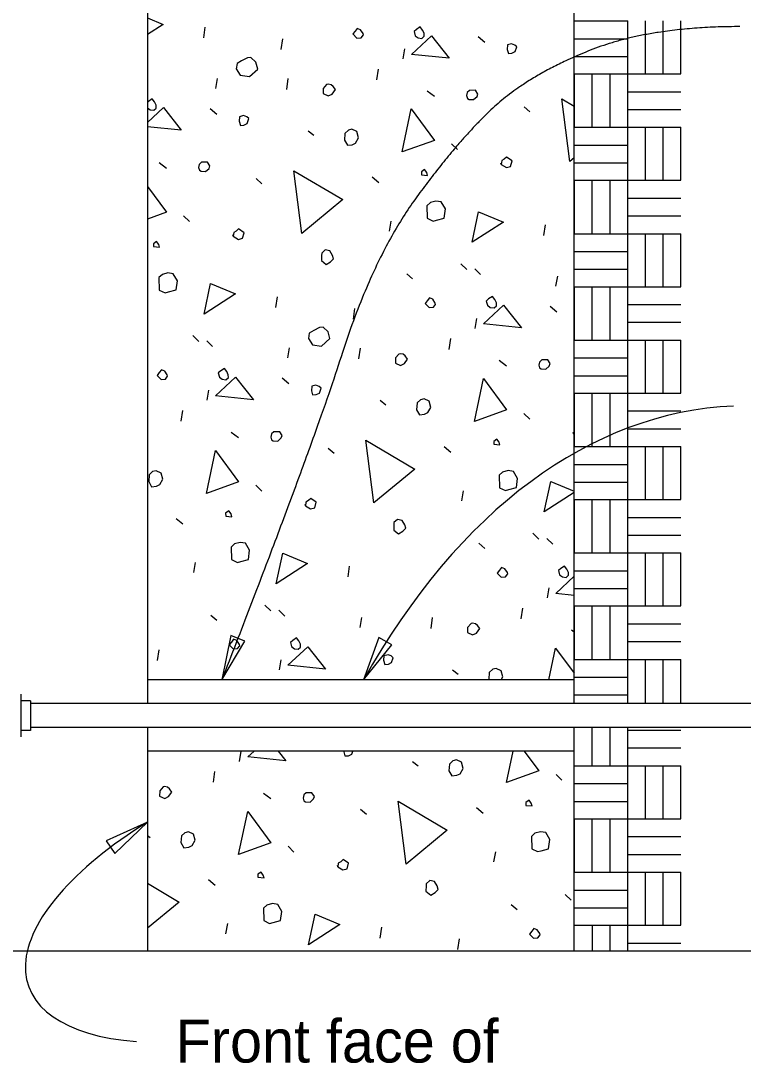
# Model space of a CAD drawing. Extents: x 0 to 30.8, y 0 to 21.2.
# Drawn here: x 25.516 to 28.054, y 11.993 to 15.653 of the extents above; entities that cross this region are included whole.
import ezdxf

# ---------------------------------------------------------------- set-up
doc = ezdxf.new("R2010")
doc.units = 0
for name, color, linetype in [('Dimension', 7, 'Continuous'), ('Lighting', 7, 'Continuous'), ('Miscellaneous', 7, 'Continuous'), ('SupstrConc', 7, 'Continuous')]:
    doc.layers.add(name, color=color, linetype=linetype)

msp = doc.modelspace()

# ---------------------------------------------------------------- linework, layer by layer
at = {"layer": 'Dimension'}
for points in [[(26.2225, 13.3392), (26.3038, 13.4751), (26.2545, 13.4943)], [(26.7207, 13.3388), (26.82, 13.4622), (26.7738, 13.488)], [(25.9607, 12.8391), (25.8165, 12.7736), (25.8461, 12.7297)]]:
    msp.add_lwpolyline(points, close=True, dxfattribs=at)
msp.add_lwpolyline([(28.7417, 12.3859), (25.4201, 12.3859), (25.4201, 12.4634), (25.3864, 12.3859), (25.3526, 12.3084), (25.3526, 12.3859), (20.9396, 12.3859)], dxfattribs=at)
for centre, major_axis, ratio, start_param, end_param in [((28.1525, 11.1408), (0.1319, -3.1595), 0.604161, 3.141595, 3.918123), ((26.5684, 12.6268), (1.0252, 0.3641), 0.417881, 2.049946, 3.892568)]:
    msp.add_ellipse(centre, major_axis=major_axis, ratio=ratio, start_param=start_param, end_param=end_param, dxfattribs=at)
msp.add_open_spline([(28.0429, 15.6332), (27.7261, 15.6332), (27.3087, 15.4672), (27.0623, 15.2459), (26.7555, 14.8283), (26.5342, 14.1391), (26.2224, 13.3392)], degree=2, dxfattribs=at)
at = {"layer": 'Lighting'}
for p, q in [((25.5162, 13.2888), (25.5162, 13.1389)), ((25.5496, 13.2658), (25.5162, 13.2658)), ((25.5496, 13.2658), (25.5496, 13.1617)), ((28.6643, 13.2555), (25.5496, 13.2555)), ((25.5496, 13.1617), (25.5162, 13.1617)), ((28.6643, 13.1721), (25.5496, 13.1721))]:
    msp.add_line(p, q, dxfattribs=at)
at = {"layer": 'Miscellaneous'}
for p, q in [((26.1587, 15.5936), (26.1641, 15.6313)), ((27.4607, 15.6534), (27.6495, 15.6534)), ((27.6495, 15.2797), (27.6495, 15.6534)), ((27.7107, 15.4672), (27.7107, 15.6534)), ((27.7732, 15.4672), (27.7732, 15.6534)), ((27.8357, 15.4672), (27.8357, 15.6534)), ((27.1228, 15.5983), (27.1462, 15.5787)), ((26.431, 15.5527), (26.4365, 15.5904)), ((27.4607, 15.5909), (27.6495, 15.5909)), ((26.8591, 15.5199), (26.8652, 15.5552)), ((27.4607, 15.5284), (27.6495, 15.5284)), ((26.2011, 15.416), (26.2072, 15.4513)), ((26.4504, 15.4129), (26.4558, 15.4506)), ((26.7676, 15.4462), (26.773, 15.4839)), ((27.4607, 15.4672), (27.8357, 15.4672)), ((27.4607, 15.4672), (27.4607, 15.2797)), ((27.5232, 15.4672), (27.5232, 15.2797)), ((27.5857, 15.4672), (27.5857, 15.2797)), ((26.9435, 15.4079), (26.9693, 15.3889)), ((27.6495, 15.4047), (27.8357, 15.4047)), ((26.181, 15.3459), (26.2044, 15.3263)), ((27.2846, 15.3518), (27.3049, 15.3339)), ((27.6495, 15.3422), (27.8357, 15.3422)), ((26.5256, 15.2674), (26.5453, 15.252)), ((27.4607, 15.2797), (27.6495, 15.2797)), ((27.6495, 14.9059), (27.6495, 15.2797)), ((27.6495, 15.2797), (27.8357, 15.2797)), ((27.7107, 15.0934), (27.7107, 15.2797)), ((27.7732, 15.0934), (27.7732, 15.2797)), ((27.8357, 15.0934), (27.8357, 15.2797)), ((27.0297, 15.2214), (27.0507, 15.2011)), ((27.4607, 15.2172), (27.6495, 15.2172)), ((26.0017, 15.1555), (26.0275, 15.1366)), ((27.4607, 15.1547), (27.6495, 15.1547)), ((26.3428, 15.0994), (26.3632, 15.0816)), ((26.7503, 15.1051), (26.7736, 15.0855)), ((27.4607, 15.0934), (27.8357, 15.0934)), ((27.4607, 15.0934), (27.4607, 14.9059)), ((27.5232, 15.0934), (27.5232, 14.9059)), ((27.5857, 15.0934), (27.5857, 14.9059)), ((27.6495, 15.0309), (27.8357, 15.0309)), ((26.0879, 14.969), (26.1089, 14.9487)), ((26.8117, 14.9145), (26.8178, 14.9497)), ((27.3541, 14.8993), (27.3595, 14.937)), ((27.6495, 14.9684), (27.8357, 14.9684)), ((27.4607, 14.9059), (27.6495, 14.9059)), ((27.6495, 14.9059), (27.8357, 14.9059)), ((27.6495, 14.5322), (27.6495, 14.9059)), ((27.7107, 14.7197), (27.7107, 14.9059)), ((27.7732, 14.7197), (27.7732, 14.9059)), ((27.8357, 14.7197), (27.8357, 14.9059)), ((27.4607, 14.8434), (27.6495, 14.8434)), ((27.0622, 14.8004), (27.0832, 14.7802)), ((26.8724, 14.7651), (26.8927, 14.7472)), ((27.1111, 14.7825), (27.132, 14.7622)), ((27.3965, 14.7218), (27.4026, 14.757)), ((27.4607, 14.7809), (27.6495, 14.7809)), ((27.4607, 14.7197), (27.8357, 14.7197)), ((27.4607, 14.7197), (27.4607, 14.5322)), ((27.5232, 14.7197), (27.5232, 14.5322)), ((27.5857, 14.7197), (27.5857, 14.5322)), ((26.4123, 14.647), (26.4177, 14.6847)), ((26.6847, 14.6061), (26.6901, 14.6438)), ((27.3765, 14.6517), (27.3998, 14.6321)), ((27.6495, 14.6572), (27.8357, 14.6572)), ((27.1128, 14.5733), (27.1188, 14.6085)), ((27.6495, 14.5947), (27.8357, 14.5947)), ((26.1205, 14.5481), (26.1414, 14.5278)), ((27.0212, 14.4996), (27.0266, 14.5373)), ((26.1693, 14.5301), (26.1902, 14.5098)), ((26.4547, 14.4694), (26.4608, 14.5047)), ((26.704, 14.4663), (26.7094, 14.504)), ((27.4607, 14.5322), (27.6495, 14.5322)), ((27.6495, 14.1584), (27.6495, 14.5322)), ((27.6495, 14.5322), (27.8357, 14.5322)), ((27.7107, 14.3459), (27.7107, 14.5322)), ((27.7732, 14.3459), (27.7732, 14.5322)), ((27.8357, 14.3459), (27.8357, 14.5322)), ((27.1971, 14.4613), (27.2229, 14.4423)), ((27.4607, 14.4697), (27.6495, 14.4697)), ((26.4347, 14.3993), (26.458, 14.3797)), ((27.4607, 14.4072), (27.6495, 14.4072)), ((26.171, 14.3209), (26.1771, 14.3562)), ((26.7792, 14.3208), (26.7989, 14.3054)), ((27.4607, 14.3459), (27.8357, 14.3459)), ((27.4607, 14.3459), (27.4607, 14.1584)), ((27.5232, 14.3459), (27.5232, 14.1584)), ((27.5857, 14.3459), (27.5857, 14.1584)), ((26.0794, 14.2472), (26.0849, 14.2849)), ((27.6495, 14.2834), (27.8357, 14.2834)), ((27.2833, 14.2747), (27.3043, 14.2545)), ((26.2553, 14.2089), (26.2811, 14.19)), ((27.6495, 14.2209), (27.8357, 14.2209)), ((26.5965, 14.1528), (26.6168, 14.135)), ((27.0039, 14.1585), (27.0273, 14.1388)), ((27.4607, 14.1584), (27.6495, 14.1584)), ((27.6495, 13.7847), (27.6495, 14.1584)), ((27.6495, 14.1584), (27.8357, 14.1584)), ((27.7107, 13.9722), (27.7107, 14.1584)), ((27.7732, 13.9722), (27.7732, 14.1584)), ((27.8357, 13.9722), (27.8357, 14.1584)), ((27.4607, 14.0959), (27.6495, 14.0959)), ((26.3416, 14.0224), (26.3625, 14.0021)), ((27.4607, 14.0334), (27.6495, 14.0334)), ((27.0653, 13.9679), (27.0714, 14.0031)), ((27.4607, 13.9722), (27.8357, 13.9722)), ((27.4607, 13.9722), (27.4607, 13.7847)), ((27.5232, 13.9722), (27.5232, 13.7847)), ((27.5857, 13.9722), (27.5857, 13.7847)), ((26.0621, 13.9061), (26.0855, 13.8865)), ((27.6495, 13.9097), (27.8357, 13.9097)), ((27.3159, 13.8538), (27.3368, 13.8336)), ((27.6495, 13.8472), (27.8357, 13.8472)), ((27.1261, 13.8185), (27.1464, 13.8006)), ((27.3647, 13.8358), (27.3857, 13.8156)), ((27.4607, 13.7847), (27.6495, 13.7847)), ((27.6495, 13.7847), (27.8357, 13.7847)), ((27.6495, 13.4109), (27.6495, 13.7847)), ((27.7107, 13.5984), (27.7107, 13.7847)), ((27.7732, 13.5984), (27.7732, 13.7847)), ((27.8357, 13.5984), (27.8357, 13.7847)), ((26.1236, 13.7155), (26.1296, 13.7508)), ((26.666, 13.7004), (26.6714, 13.7381)), ((27.4607, 13.7222), (27.6495, 13.7222)), ((27.3664, 13.6267), (27.3725, 13.6619)), ((27.4607, 13.6597), (27.6495, 13.6597)), ((26.3741, 13.6015), (26.3951, 13.5812)), ((26.4229, 13.5835), (26.4439, 13.5632)), ((27.2749, 13.553), (27.2803, 13.5906)), ((27.4607, 13.5984), (27.8357, 13.5984)), ((27.4607, 13.5984), (27.4607, 13.4109)), ((27.5232, 13.5984), (27.5232, 13.4109)), ((27.5857, 13.5984), (27.5857, 13.4109)), ((26.1843, 13.5661), (26.2046, 13.5483)), ((26.7084, 13.5228), (26.7144, 13.5581)), ((26.9577, 13.5197), (26.9631, 13.5574)), ((27.4508, 13.5147), (27.4607, 13.5073)), ((27.6495, 13.5359), (27.8357, 13.5359)), ((27.6495, 13.4734), (27.8357, 13.4734)), ((25.9965, 13.4071), (26.002, 13.4448)), ((26.4246, 13.3743), (26.4307, 13.4096)), ((27.4607, 13.4109), (27.6495, 13.4109)), ((27.6495, 13.2555), (27.6495, 13.411)), ((27.6495, 13.4109), (27.8357, 13.4109)), ((27.7107, 13.2555), (27.7107, 13.411)), ((27.7732, 13.2555), (27.7732, 13.411)), ((27.8357, 13.2555), (27.8357, 13.411)), ((27.0329, 13.3742), (27.0525, 13.3588)), ((27.4607, 13.3388), (25.9607, 13.3388)), ((27.4607, 13.3484), (27.6495, 13.3484)), ((27.4607, 13.2859), (27.6495, 13.2859)), ((27.5232, 13.1721), (27.5232, 13.0372)), ((27.5857, 13.1721), (27.5857, 13.0372)), ((27.6495, 13.0372), (27.6495, 13.1721)), ((27.6495, 13.1622), (27.8357, 13.1622)), ((27.4607, 13.0888), (25.9607, 13.0888)), ((26.2844, 13.0528), (26.2905, 13.0881)), ((27.6495, 13.0997), (27.8357, 13.0997)), ((26.8927, 13.0527), (26.9123, 13.0373)), ((27.4607, 13.0372), (27.6495, 13.0372)), ((27.6495, 12.6634), (27.6495, 13.0372)), ((27.6495, 13.0372), (27.8357, 13.0372)), ((27.7107, 12.8509), (27.7107, 13.0372)), ((27.7732, 12.8509), (27.7732, 13.0372)), ((27.8357, 12.8509), (27.8357, 13.0372)), ((26.1929, 12.9791), (26.1983, 13.0168)), ((27.3968, 13.0066), (27.4177, 12.9864)), ((27.4607, 12.9747), (27.6495, 12.9747)), ((26.3688, 12.9408), (26.3946, 12.9218)), ((27.1174, 12.8903), (27.1407, 12.8707)), ((27.4607, 12.9122), (27.6495, 12.9122)), ((26.7099, 12.8847), (26.7303, 12.8668)), ((27.4607, 12.8509), (27.8357, 12.8509)), ((27.4607, 12.8509), (27.4607, 12.6634)), ((27.5232, 12.8509), (27.5232, 12.6634)), ((27.5857, 12.8509), (27.5857, 12.6634)), ((25.9607, 12.7926), (25.9706, 12.7849)), ((27.6495, 12.7884), (27.8357, 12.7884)), ((26.455, 12.7543), (26.476, 12.734)), ((27.1788, 12.6997), (27.1849, 12.735)), ((27.6495, 12.7259), (27.8357, 12.7259)), ((26.1756, 12.638), (26.199, 12.6184)), ((27.4607, 12.6634), (27.6495, 12.6634)), ((27.6495, 12.386), (27.6495, 12.6635)), ((27.6495, 12.6634), (27.8357, 12.6634)), ((27.7107, 12.4772), (27.7107, 12.6634)), ((27.7732, 12.4772), (27.7732, 12.6634)), ((27.8357, 12.4772), (27.8357, 12.6634)), ((27.4607, 12.6009), (27.6495, 12.6009)), ((27.4293, 12.5857), (27.4503, 12.5654)), ((27.2395, 12.5504), (27.2598, 12.5325)), ((27.4607, 12.5384), (27.6495, 12.5384)), ((26.237, 12.4474), (26.2431, 12.4827)), ((26.7794, 12.4323), (26.7848, 12.47)), ((27.4607, 12.4772), (27.8357, 12.4772)), ((27.5233, 12.4772), (27.5233, 12.386)), ((27.5858, 12.4772), (27.5858, 12.386)), ((27.0518, 12.3914), (27.0572, 12.4291)), ((27.6495, 12.4147), (27.8357, 12.4147))]:
    msp.add_line(p, q, dxfattribs=at)
for points in [[(25.9607, 15.664), (26.0166, 15.6409), (25.9607, 15.605)], [(26.902, 15.6013), (26.9119, 15.5935), (26.9252, 15.5919), (26.9336, 15.5994), (26.9334, 15.6097), (26.9278, 15.6211), (26.9197, 15.6319), (26.9065, 15.6232), (26.8981, 15.6157), (26.902, 15.6013)], [(26.683, 15.6073), (26.6972, 15.593), (26.7123, 15.5944), (26.72, 15.6043), (26.7187, 15.6091), (26.71, 15.6223), (26.6984, 15.6269), (26.6907, 15.6171), (26.683, 15.6073)], [(26.8886, 15.5355), (26.959, 15.601), (27.0216, 15.522), (26.8886, 15.5355)], [(27.2254, 15.5533), (27.2293, 15.5388), (27.242, 15.5397), (27.2535, 15.5453), (27.2593, 15.5624), (27.2525, 15.5683), (27.2409, 15.573), (27.2264, 15.5691), (27.2254, 15.5533)], [(26.2733, 15.4846), (26.287, 15.4623), (26.3192, 15.458), (26.3485, 15.484), (26.342, 15.5081), (26.3248, 15.5242), (26.3121, 15.5234), (26.2916, 15.5128), (26.276, 15.5034), (26.2733, 15.4846)], [(26.5789, 15.4163), (26.5786, 15.3981), (26.5963, 15.3899), (26.6101, 15.3962), (26.6214, 15.4122), (26.6133, 15.423), (26.6066, 15.4289), (26.5956, 15.4311), (26.5908, 15.4299), (26.5789, 15.4163)], [(25.9607, 15.3485), (25.9701, 15.3412), (25.9834, 15.3396), (25.9918, 15.347), (25.9916, 15.3573), (25.986, 15.3687), (25.9779, 15.3795), (25.9647, 15.3708), (25.9607, 15.3673)], [(27.0852, 15.3812), (27.0913, 15.3776), (27.1071, 15.3767), (27.1197, 15.3878), (27.1226, 15.3964), (27.1139, 15.4095), (27.0932, 15.4092), (27.0849, 15.4018), (27.0826, 15.3908), (27.0852, 15.3812)], [(27.4449, 15.1592), (27.417, 15.3795), (27.4607, 15.3537)], [(25.9607, 15.2961), (26.0173, 15.3486), (26.0798, 15.2697), (25.9607, 15.2818)], [(26.8561, 15.193), (26.8882, 15.3439), (26.9695, 15.2337), (26.8561, 15.193)], [(26.2837, 15.301), (26.2875, 15.2865), (26.3003, 15.2873), (26.3117, 15.293), (26.3175, 15.31), (26.3107, 15.316), (26.2991, 15.3206), (26.2846, 15.3168), (26.2837, 15.301)], [(26.6549, 15.2581), (26.6535, 15.2344), (26.6635, 15.2164), (26.681, 15.2185), (26.6925, 15.2242), (26.7031, 15.2425), (26.6973, 15.2643), (26.6795, 15.2725), (26.6675, 15.2692), (26.6549, 15.2581)], [(26.1434, 15.1288), (26.1496, 15.1253), (26.1654, 15.1243), (26.1779, 15.1355), (26.1808, 15.144), (26.1721, 15.1572), (26.1515, 15.1569), (26.1431, 15.1494), (26.1409, 15.1385), (26.1434, 15.1288)], [(27.2043, 15.1491), (27.2227, 15.1385), (27.2372, 15.1424), (27.2423, 15.1619), (27.2233, 15.1749), (27.215, 15.1675), (27.2059, 15.1625), (27.2043, 15.1491), (27.2031, 15.1539)], [(27.4607, 15.1722), (27.4449, 15.1592)], [(26.5032, 14.9069), (26.4752, 15.1271), (26.6473, 15.0257), (26.5032, 14.9069)], [(26.9242, 15.1128), (26.9454, 15.1108), (26.9429, 15.1204), (26.9348, 15.1312), (26.924, 15.1232), (26.9242, 15.1128)], [(25.9607, 15.0721), (26.0277, 14.9813), (25.9607, 14.9573)], [(26.943, 15.004), (26.9443, 14.9604), (26.9651, 14.9504), (26.9772, 14.9536), (27.0038, 14.9608), (27.0081, 14.993), (26.9937, 15.0176), (26.9749, 15.0203), (26.9555, 15.0151), (26.943, 15.004)], [(27.1016, 14.8757), (27.1247, 14.9828), (27.212, 14.9467), (27.1016, 14.8757)], [(26.2626, 14.8967), (26.2809, 14.8861), (26.2954, 14.89), (26.3006, 14.9095), (26.2815, 14.9225), (26.2732, 14.9151), (26.2642, 14.9101), (26.2626, 14.8967), (26.2613, 14.9016)], [(25.9824, 14.8605), (26.0037, 14.8584), (26.0011, 14.8681), (25.993, 14.8789), (25.9822, 14.8708), (25.9824, 14.8605)], [(26.573, 14.8298), (26.5727, 14.8116), (26.5893, 14.7979), (26.6049, 14.8073), (26.615, 14.8178), (26.6118, 14.8298), (26.6024, 14.8455), (26.586, 14.8488), (26.5734, 14.8377), (26.573, 14.8298)], [(26.0012, 14.7517), (26.0026, 14.708), (26.0233, 14.6981), (26.0354, 14.7013), (26.062, 14.7084), (26.0663, 14.7406), (26.0519, 14.7652), (26.0331, 14.768), (26.0138, 14.7628), (26.0012, 14.7517)], [(26.1598, 14.6233), (26.1829, 14.7305), (26.2702, 14.6943), (26.1598, 14.6233)], [(26.9366, 14.6607), (26.9508, 14.6463), (26.966, 14.6478), (26.9737, 14.6576), (26.9724, 14.6625), (26.9637, 14.6757), (26.9521, 14.6803), (26.9444, 14.6705), (26.9366, 14.6607)], [(27.1557, 14.6546), (27.1655, 14.6469), (27.1789, 14.6453), (27.1872, 14.6527), (27.1871, 14.6631), (27.1814, 14.6745), (27.1733, 14.6853), (27.1601, 14.6766), (27.1518, 14.6691), (27.1557, 14.6546)], [(27.1422, 14.5889), (27.2127, 14.6544), (27.2752, 14.5754), (27.1422, 14.5889)], [(26.5269, 14.5379), (26.5407, 14.5157), (26.5729, 14.5114), (26.6021, 14.5374), (26.5957, 14.5615), (26.5784, 14.5776), (26.5657, 14.5768), (26.5453, 14.5661), (26.5297, 14.5568), (26.5269, 14.5379)], [(26.8325, 14.4697), (26.8322, 14.4515), (26.8499, 14.4433), (26.8638, 14.4496), (26.875, 14.4656), (26.867, 14.4764), (26.8602, 14.4823), (26.8492, 14.4845), (26.8444, 14.4832), (26.8325, 14.4697)], [(27.3389, 14.4346), (27.345, 14.431), (27.3608, 14.4301), (27.3733, 14.4412), (27.3762, 14.4497), (27.3675, 14.4629), (27.3469, 14.4626), (27.3385, 14.4552), (27.3363, 14.4442), (27.3389, 14.4346)], [(25.9949, 14.4083), (26.0091, 14.394), (26.0242, 14.3955), (26.0319, 14.4053), (26.0306, 14.4101), (26.0219, 14.4233), (26.0103, 14.428), (26.0026, 14.4181), (25.9949, 14.4083)], [(26.2139, 14.4023), (26.2237, 14.3946), (26.2371, 14.393), (26.2455, 14.4004), (26.2453, 14.4107), (26.2396, 14.4221), (26.2316, 14.4329), (26.2184, 14.4242), (26.21, 14.4168), (26.2139, 14.4023)], [(26.2004, 14.3366), (26.2709, 14.402), (26.3335, 14.323), (26.2004, 14.3366)], [(27.1098, 14.2464), (27.1418, 14.3973), (27.2231, 14.2871), (27.1098, 14.2464)], [(26.5373, 14.3544), (26.5412, 14.3399), (26.5539, 14.3407), (26.5653, 14.3464), (26.5711, 14.3634), (26.5643, 14.3694), (26.5527, 14.374), (26.5383, 14.3702), (26.5373, 14.3544)], [(26.9086, 14.3115), (26.9071, 14.2878), (26.9171, 14.2698), (26.9347, 14.2719), (26.9461, 14.2776), (26.9567, 14.2959), (26.9509, 14.3177), (26.9332, 14.3259), (26.9211, 14.3226), (26.9086, 14.3115)], [(26.3971, 14.1822), (26.4032, 14.1787), (26.419, 14.1777), (26.4315, 14.1889), (26.4344, 14.1974), (26.4257, 14.2106), (26.4051, 14.2102), (26.3967, 14.2028), (26.3945, 14.1919), (26.3971, 14.1822)], [(27.4607, 14.2165), (27.4596, 14.2159), (27.458, 14.2025), (27.4567, 14.2073)], [(26.7568, 13.9602), (26.7288, 14.1805), (26.9009, 14.0791), (26.7568, 13.9602)], [(27.1778, 14.1662), (27.1991, 14.1642), (27.1965, 14.1738), (27.1884, 14.1846), (27.1777, 14.1765), (27.1778, 14.1662)], [(27.458, 14.2025), (27.4607, 14.2009)], [(26.168, 13.994), (26.2, 14.1449), (26.2813, 14.0347), (26.168, 13.994)], [(25.9668, 14.0591), (25.9654, 14.0355), (25.9754, 14.0174), (25.9929, 14.0196), (26.0043, 14.0252), (26.0149, 14.0436), (26.0091, 14.0653), (25.9914, 14.0735), (25.9793, 14.0703), (25.9668, 14.0591)], [(27.1966, 14.0574), (27.198, 14.0138), (27.2188, 14.0038), (27.2308, 14.007), (27.2574, 14.0142), (27.2617, 14.0464), (27.2473, 14.071), (27.2285, 14.0737), (27.2092, 14.0685), (27.1966, 14.0574)], [(27.3553, 13.9291), (27.3783, 14.0362), (27.4607, 14.0021)], [(27.4607, 13.9969), (27.3553, 13.9291)], [(26.5162, 13.9501), (26.5346, 13.9395), (26.5491, 13.9434), (26.5542, 13.9629), (26.5352, 13.9759), (26.5268, 13.9685), (26.5178, 13.9635), (26.5162, 13.9501), (26.5149, 13.955)], [(26.236, 13.9139), (26.2573, 13.9118), (26.2547, 13.9215), (26.2467, 13.9323), (26.2359, 13.9242), (26.236, 13.9139)], [(26.8266, 13.8832), (26.8263, 13.865), (26.8429, 13.8513), (26.8585, 13.8607), (26.8687, 13.8712), (26.8654, 13.8832), (26.8561, 13.8989), (26.8396, 13.9022), (26.8271, 13.8911), (26.8266, 13.8832)], [(26.2549, 13.8051), (26.2562, 13.7614), (26.277, 13.7515), (26.2891, 13.7547), (26.3156, 13.7618), (26.3199, 13.794), (26.3056, 13.8186), (26.2867, 13.8214), (26.2674, 13.8162), (26.2549, 13.8051)], [(26.4135, 13.6767), (26.4365, 13.7838), (26.5239, 13.7477), (26.4135, 13.6767)], [(27.1903, 13.7141), (27.2045, 13.6997), (27.2196, 13.7012), (27.2273, 13.711), (27.226, 13.7159), (27.2173, 13.7291), (27.2057, 13.7337), (27.198, 13.7239), (27.1903, 13.7141)], [(27.4093, 13.708), (27.4191, 13.7003), (27.4325, 13.6987), (27.4409, 13.7061), (27.4407, 13.7164), (27.435, 13.7279), (27.427, 13.7387), (27.4138, 13.7299), (27.4054, 13.7225), (27.4093, 13.708)], [(27.3959, 13.6423), (27.4607, 13.7026)], [(27.4607, 13.6357), (27.3959, 13.6423)], [(27.0862, 13.5231), (27.0859, 13.5049), (27.1036, 13.4967), (27.1174, 13.503), (27.1287, 13.519), (27.1206, 13.5297), (27.1138, 13.5357), (27.1029, 13.5379), (27.0981, 13.5366), (27.0862, 13.5231)], [(26.2485, 13.4617), (26.2627, 13.4474), (26.2778, 13.4489), (26.2855, 13.4587), (26.2843, 13.4635), (26.2755, 13.4767), (26.2639, 13.4814), (26.2562, 13.4715), (26.2485, 13.4617)], [(26.4675, 13.4557), (26.4774, 13.448), (26.4907, 13.4464), (26.4991, 13.4538), (26.4989, 13.4641), (26.4933, 13.4755), (26.4852, 13.4863), (26.472, 13.4776), (26.4636, 13.4702), (26.4675, 13.4557)], [(26.4541, 13.39), (26.5245, 13.4554), (26.5871, 13.3764), (26.4541, 13.39)], [(27.3717, 13.3388), (27.3954, 13.4507), (27.4607, 13.3621)], [(26.791, 13.4078), (26.7948, 13.3933), (26.8076, 13.3941), (26.819, 13.3997), (26.8248, 13.4168), (26.818, 13.4228), (26.8064, 13.4274), (26.7919, 13.4235), (26.791, 13.4078)], [(27.1622, 13.3649), (27.1608, 13.3412), (27.1621, 13.3388)], [(27.2043, 13.3388), (27.2104, 13.3493), (27.2045, 13.3711), (27.1868, 13.3793), (27.1747, 13.376), (27.1622, 13.3649)], [(26.3139, 13.0685), (26.3358, 13.0888)], [(26.4201, 13.0888), (26.4469, 13.0549), (26.3139, 13.0685)], [(26.6508, 13.0863), (26.6546, 13.0718), (26.6674, 13.0726), (26.6788, 13.0782), (26.6824, 13.0888)], [(26.6509, 13.0888), (26.6508, 13.0863)], [(27.2232, 12.9782), (27.2467, 13.0888)], [(27.285, 13.0888), (27.3365, 13.019), (27.2232, 12.9782)], [(27.022, 13.0434), (27.0206, 13.0197), (27.0306, 13.0017), (27.0481, 13.0038), (27.0596, 13.0094), (27.0702, 13.0278), (27.0644, 13.0495), (27.0466, 13.0577), (27.0346, 13.0545), (27.022, 13.0434)], [(26.0042, 12.9492), (26.0039, 12.931), (26.0216, 12.9228), (26.0355, 12.9291), (26.0467, 12.9451), (26.0386, 12.9559), (26.0319, 12.9618), (26.0209, 12.9641), (26.0161, 12.9628), (26.0042, 12.9492)], [(26.5105, 12.9141), (26.5167, 12.9106), (26.5324, 12.9096), (26.545, 12.9207), (26.5479, 12.9293), (26.5392, 12.9425), (26.5186, 12.9421), (26.5102, 12.9347), (26.508, 12.9238), (26.5105, 12.9141)], [(26.8702, 12.6921), (26.8423, 12.9124), (27.0144, 12.811), (26.8702, 12.6921)], [(27.2913, 12.8981), (27.3125, 12.896), (27.3099, 12.9057), (27.3019, 12.9165), (27.2911, 12.9084), (27.2913, 12.8981)], [(26.2814, 12.7259), (26.3135, 12.8768), (26.3948, 12.7666), (26.2814, 12.7259)], [(26.0802, 12.791), (26.0788, 12.7674), (26.0888, 12.7493), (26.1064, 12.7514), (26.1178, 12.7571), (26.1284, 12.7755), (26.1226, 12.7972), (26.1049, 12.8054), (26.0928, 12.8022), (26.0802, 12.791)], [(27.3101, 12.7893), (27.3114, 12.7456), (27.3322, 12.7357), (27.3443, 12.7389), (27.3709, 12.746), (27.3752, 12.7782), (27.3608, 12.8029), (27.342, 12.8056), (27.3226, 12.8004), (27.3101, 12.7893)], [(26.6297, 12.682), (26.648, 12.6714), (26.6625, 12.6753), (26.6677, 12.6948), (26.6486, 12.7078), (26.6403, 12.7004), (26.6313, 12.6954), (26.6297, 12.682), (26.6284, 12.6868)], [(26.3495, 12.6458), (26.3708, 12.6437), (26.3682, 12.6534), (26.3601, 12.6641), (26.3493, 12.6561), (26.3495, 12.6458)], [(26.9401, 12.6151), (26.9398, 12.5969), (26.9564, 12.5832), (26.972, 12.5926), (26.9821, 12.603), (26.9789, 12.6151), (26.9695, 12.6307), (26.9531, 12.6341), (26.9405, 12.623), (26.9401, 12.6151)], [(25.9607, 12.6246), (26.0726, 12.5586), (25.9607, 12.4664)], [(26.3683, 12.5369), (26.3697, 12.4933), (26.3904, 12.4833), (26.4025, 12.4866), (26.4291, 12.4937), (26.4334, 12.5259), (26.419, 12.5505), (26.4002, 12.5532), (26.3809, 12.5481), (26.3683, 12.5369)], [(26.5269, 12.4086), (26.55, 12.5157), (26.6373, 12.4796), (26.5269, 12.4086)], [(27.3037, 12.4459), (27.3179, 12.4316), (27.3331, 12.4331), (27.3408, 12.4429), (27.3395, 12.4477), (27.3308, 12.4609), (27.3192, 12.4656), (27.3115, 12.4558), (27.3037, 12.4459)]]:
    msp.add_lwpolyline(points, dxfattribs=at)
at = {"layer": 'SupstrConc'}
for p, q in [((27.4607, 13.2555), (27.4607, 17.3442)), ((25.9607, 17.2997), (25.9607, 13.2555)), ((25.9607, 13.1721), (25.9607, 12.386)), ((27.4607, 12.386), (27.4607, 13.1721))]:
    msp.add_line(p, q, dxfattribs=at)

# ---------------------------------------------------------------- texts
at = {"layer": 'Dimension'}
msp.add_text('Front face of', height=0.1512, dxfattribs=at).set_placement((26.0604, 11.9949))

doc.saveas('drawing.dxf')
